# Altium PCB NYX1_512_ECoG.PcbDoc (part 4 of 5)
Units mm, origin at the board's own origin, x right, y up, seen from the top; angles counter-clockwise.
Board outline 46.64 x 13 mm, 4 copper layers (metal 2, via, metal1, electrodes), stack 0.007 mm thick; 9 components, 547 nets, 1871 pads, 0 vias.
Unrouted connection lines stored in the file: 652.
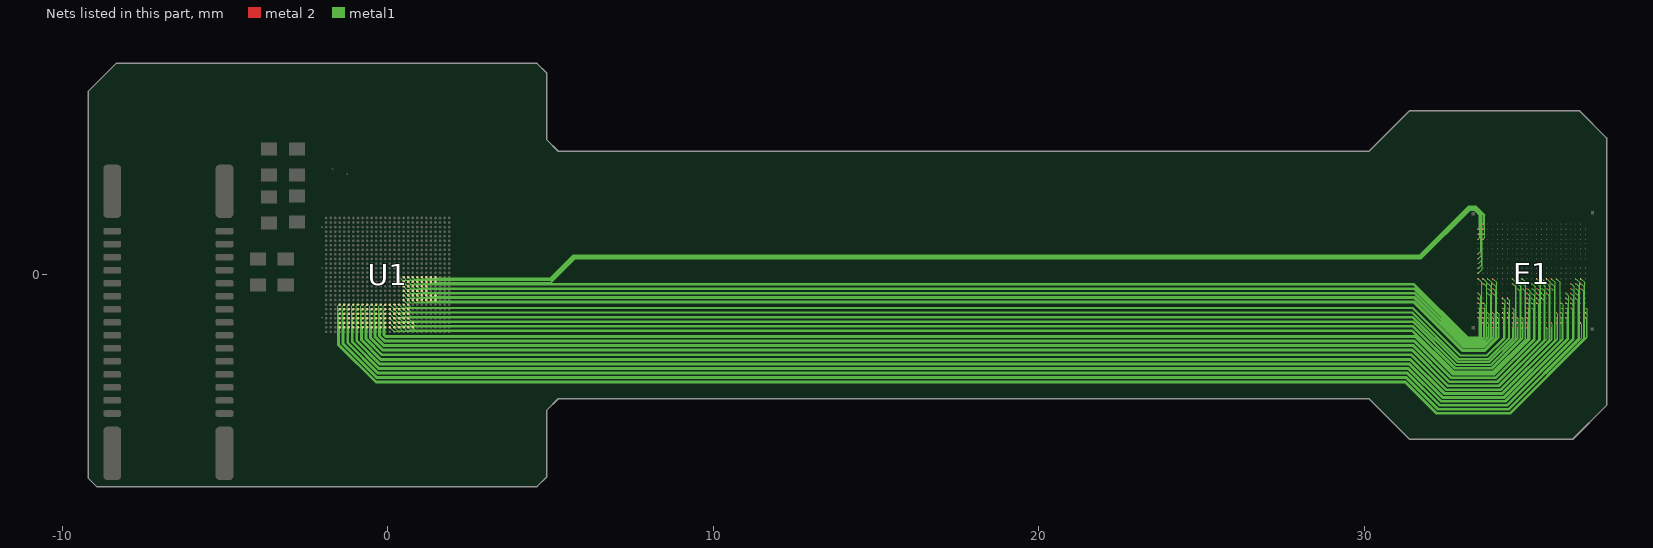
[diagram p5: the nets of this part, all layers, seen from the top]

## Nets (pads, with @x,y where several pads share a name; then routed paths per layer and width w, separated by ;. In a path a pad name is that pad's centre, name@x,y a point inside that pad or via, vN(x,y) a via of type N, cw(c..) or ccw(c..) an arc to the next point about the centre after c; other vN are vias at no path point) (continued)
el286: E1.325 pad.34@34.691,-0.425 U1.J24 | length 36.6
  metal 2 w0.012: pad.34@34.691,-0.425 E1.325@34.691,-0.406
  metal1 w0.005: U1.J24@0.77,-1.469 0.837,-1.536 3.141,-1.536 30.141,-1.536 31.486,-1.536 32.787,-2.836 33.916,-2.836 34.791,-1.962 34.791,-0.506 34.71,-0.425 pad.34@34.691,-0.425
el287: E1.326 pad.34@34.841,-0.425 U1.J25 | length 36.7
  metal 2 w0.012: pad.34@34.841,-0.425 E1.326@34.841,-0.406
  metal1 w0.005: U1.J25@0.77,-1.609 0.837,-1.676 31.468,-1.676 32.739,-2.946 33.962,-2.946 34.941,-1.967 34.941,-0.506 34.86,-0.425 pad.34@34.841,-0.425
el288: E1.460 pad.34@34.241,-1.325 U1.K20 | length 35.1
  metal 2 w0.012: pad.34@34.241,-1.325 E1.460@34.241,-1.306
  metal1 w0.005: U1.K20@0.63,-0.909 0.707,-0.986 30.141,-0.986 31.49,-0.986 32.95,-2.446 33.755,-2.446 34.281,-1.92 34.281,-1.346 34.26,-1.325 pad.34@34.241,-1.325
el289: E1.461 pad.34@34.391,-1.325 U1.K21 | length 35.3
  metal 2 w0.012: pad.34@34.391,-1.325 E1.461@34.391,-1.306
  metal1 w0.005: U1.K21@0.63,-1.049 0.707,-1.126 3.141,-1.126 ; 3.141,-1.126 31.473,-1.126 32.903,-2.556 33.8,-2.556 34.431,-1.926 34.431,-1.346 34.41,-1.325 pad.34@34.391,-1.325
el290: E1.504 pad.34@34.541,-1.625 U1.K22 | length 35.2
  metal 2 w0.012: pad.34@34.541,-1.625 E1.504@34.541,-1.606
  metal1 w0.005: U1.K22@0.63,-1.189 0.707,-1.266 31.486,-1.266 32.866,-2.646 33.838,-2.646 34.561,-1.923 34.561,-1.645 pad.34@34.541,-1.625
el291: E1.301 pad.34@34.541,-0.275 U1.K23 | length 36.7
  metal 2 w0.012: pad.34@34.541,-0.275 E1.301@34.541,-0.256
  metal1 w0.005: U1.K23@0.63,-1.329 0.707,-1.406 30.141,-1.406 31.498,-1.406 32.828,-2.736 33.875,-2.736 34.651,-1.96 34.651,-0.366 34.56,-0.275 pad.34@34.541,-0.275
el292: E1.302 pad.34@34.691,-0.275 U1.K24 | length 36.9
  metal 2 w0.012: pad.34@34.691,-0.275 E1.302@34.691,-0.256
  metal1 w0.005: U1.K24@0.63,-1.469 0.707,-1.546 3.141,-1.546 30.141,-1.546 31.482,-1.546 32.782,-2.846 33.92,-2.846 34.801,-1.966 34.801,-0.366 34.71,-0.275 pad.34@34.691,-0.275
el293: E1.303 pad.34@34.841,-0.275 U1.K25 | length 37.1
  metal 2 w0.012: pad.34@34.841,-0.275 E1.303@34.841,-0.256
  metal1 w0.005: U1.K25@0.63,-1.609 0.707,-1.686 31.464,-1.686 32.735,-2.957 33.966,-2.957 34.951,-1.971 34.951,-0.366 34.86,-0.275 pad.34@34.841,-0.275
el294: E1.437 pad.34@34.241,-1.175 U1.L20 | length 35.5
  metal 2 w0.012: pad.34@34.241,-1.175 E1.437@34.241,-1.156
  metal1 w0.005: U1.L20@0.49,-0.909 0.577,-0.996 30.141,-0.996 31.486,-0.996 32.946,-2.456 33.759,-2.456 34.291,-1.924 34.291,-1.206 34.26,-1.175 pad.34@34.241,-1.175
el295: E1.438 pad.34@34.391,-1.175 U1.L21 | length 35.6
  metal 2 w0.012: pad.34@34.391,-1.175 E1.438@34.391,-1.156
  metal1 w0.005: U1.L21@0.49,-1.049 0.577,-1.136 3.141,-1.136 30.141,-1.136 31.469,-1.136 32.899,-2.566 33.804,-2.566 34.441,-1.93 34.441,-1.206 34.41,-1.175 pad.34@34.391,-1.175
el296: E1.484 pad.34@34.541,-1.475 U1.L22 | length 35.5
  metal 2 w0.012: pad.34@34.541,-1.475 E1.484@34.541,-1.456
  metal1 w0.005: U1.L22@0.49,-1.189 0.577,-1.276 31.481,-1.276 32.862,-2.656 33.842,-2.656 34.571,-1.927 34.571,-1.505 pad.34@34.541,-1.475
el297: E1.278 pad.34@34.541,-0.125 U1.L23 | length 37
  metal 2 w0.012: pad.34@34.541,-0.125 E1.278@34.541,-0.106
  metal1 w0.005: U1.L23@0.49,-1.329 0.577,-1.416 30.141,-1.416 31.494,-1.416 32.824,-2.746 33.879,-2.746 34.661,-1.964 34.661,-0.226 34.56,-0.125 pad.34@34.541,-0.125
el298: E1.279 pad.34@34.691,-0.125 U1.L24 | length 37.2
  metal 2 w0.012: pad.34@34.691,-0.125 E1.279@34.691,-0.106
  metal1 w0.005: U1.L24@0.49,-1.469 0.577,-1.556 3.141,-1.556 30.141,-1.556 31.478,-1.556 32.778,-2.856 33.925,-2.856 34.811,-1.97 34.811,-0.226 34.71,-0.125 pad.34@34.691,-0.125
el299: E1.280 pad.34@34.841,-0.125 U1.L25 | length 37.4
  metal 2 w0.012: pad.34@34.841,-0.125 E1.280@34.841,-0.106
  metal1 w0.005: U1.L25@0.49,-1.609 0.577,-1.696 30.137,-1.696 31.46,-1.696 32.731,-2.967 33.97,-2.967 34.961,-1.976 34.961,-0.226 34.86,-0.125 pad.34@34.841,-0.125
el300: E1.414 pad.34@34.241,-1.025 U1.M20 | length 35.8
  metal 2 w0.012: pad.34@34.241,-1.025 E1.414@34.241,-1.006
  metal1 w0.005: U1.M20@0.35,-0.909 0.447,-1.006 30.141,-1.006 31.481,-1.006 32.942,-2.466 33.763,-2.466 34.301,-1.928 34.301,-1.066 34.26,-1.025 pad.34@34.241,-1.025
el301: E1.415 pad.34@34.391,-1.025 U1.M21 | length 36
  metal 2 w0.012: pad.34@34.391,-1.025 E1.415@34.391,-1.006
  metal1 w0.005: U1.M21@0.35,-1.049 0.447,-1.146 3.141,-1.146 30.141,-1.146 31.465,-1.146 32.895,-2.576 33.809,-2.576 34.451,-1.934 34.451,-1.066 34.41,-1.025 pad.34@34.391,-1.025
el302: E1.462 pad.34@34.541,-1.325 U1.M22 | length 35.8
  metal 2 w0.012: pad.34@34.541,-1.325 E1.462@34.541,-1.306
  metal1 w0.005: U1.M22@0.35,-1.189 0.447,-1.286 31.477,-1.286 32.858,-2.666 33.846,-2.666 34.581,-1.931 34.581,-1.346 34.56,-1.325 pad.34@34.541,-1.325
el303: E1.505 pad.34@34.691,-1.625 U1.M23 | length 35.6
  metal 2 w0.012: pad.34@34.691,-1.625 E1.505@34.691,-1.606
  metal1 w0.005: U1.M23@0.35,-1.329 0.447,-1.426 3.141,-1.426 30.141,-1.426 31.49,-1.426 32.82,-2.756 33.883,-2.756 34.711,-1.929 34.711,-1.645 pad.34@34.691,-1.625
el304: E1.506 pad.34@34.841,-1.625 U1.M24 | length 35.8
  metal 2 w0.012: pad.34@34.841,-1.625 E1.506@34.841,-1.606
  metal1 w0.005: U1.M24@0.35,-1.469 0.447,-1.566 3.141,-1.566 30.141,-1.566 31.473,-1.566 32.774,-2.866 33.929,-2.866 34.861,-1.934 34.861,-1.645 pad.34@34.841,-1.625
el305: E1.507 pad.34@34.991,-1.625 U1.M25 | length 36
  metal 2 w0.012: pad.34@34.991,-1.625 E1.507@34.991,-1.606
  metal1 w0.005: U1.M25@0.35,-1.609 0.447,-1.706 3.141,-1.706 31.456,-1.706 32.726,-2.977 33.974,-2.977 35.011,-1.94 35.011,-1.645 pad.34@34.991,-1.625
el306: E1.391 pad.34@34.241,-0.875 U1.N20 | length 36.1
  metal 2 w0.012: pad.34@34.241,-0.875 E1.391@34.241,-0.856
  metal1 w0.005: U1.N20@0.21,-0.909 0.317,-1.016 30.141,-1.016 31.477,-1.016 32.937,-2.476 33.767,-2.476 34.311,-1.933 34.311,-0.926 34.26,-0.875 pad.34@34.241,-0.875
el307: E1.392 pad.34@34.391,-0.875 U1.N21 | length 36.3
  metal 2 w0.012: pad.34@34.391,-0.875 E1.392@34.391,-0.856
  metal1 w0.005: U1.N21@0.21,-1.049 0.317,-1.156 3.141,-1.156 30.141,-1.156 31.46,-1.156 32.891,-2.586 33.813,-2.586 34.461,-1.938 34.461,-0.926 34.41,-0.875 pad.34@34.391,-0.875
el308: E1.439 pad.34@34.541,-1.175 U1.N22 | length 36.1
  metal 2 w0.012: pad.34@34.541,-1.175 E1.439@34.541,-1.156
  metal1 w0.005: U1.N22@0.21,-1.189 0.317,-1.296 31.473,-1.296 32.853,-2.676 33.85,-2.676 34.591,-1.935 34.591,-1.206 34.56,-1.175 pad.34@34.541,-1.175
el309: E1.485 pad.34@34.691,-1.475 U1.N23 | length 35.9
  metal 2 w0.012: pad.34@34.691,-1.475 E1.485@34.691,-1.456
  metal1 w0.005: U1.N23@0.21,-1.329 0.317,-1.436 3.141,-1.436 30.141,-1.436 31.486,-1.436 32.816,-2.766 33.887,-2.766 34.721,-1.933 34.721,-1.505 pad.34@34.691,-1.475
el310: E1.486 pad.34@34.841,-1.475 U1.N24 | length 36.1
  metal 2 w0.012: pad.34@34.841,-1.475 E1.486@34.841,-1.456
  metal1 w0.005: U1.N24@0.21,-1.469 0.317,-1.576 3.141,-1.576 30.141,-1.576 31.469,-1.576 32.77,-2.876 33.933,-2.876 34.871,-1.938 34.871,-1.505 pad.34@34.841,-1.475
el311: E1.487 pad.34@34.991,-1.475 U1.N25 | length 36.3
  metal 2 w0.012: pad.34@34.991,-1.475 E1.487@34.991,-1.456
  metal1 w0.005: U1.N25@0.21,-1.609 0.317,-1.716 3.141,-1.716 31.452,-1.716 32.722,-2.987 33.978,-2.987 35.021,-1.944 35.021,-1.505 pad.34@34.991,-1.475
el312: E1.368 pad.34@34.241,-0.725 U1.P20 | length 36.4
  metal 2 w0.012: pad.34@34.241,-0.725 E1.368@34.241,-0.706
  metal1 w0.005: U1.P20@0.07,-0.909 0.188,-1.026 30.141,-1.026 31.473,-1.026 32.933,-2.486 33.771,-2.486 34.321,-1.937 34.321,-0.786 34.26,-0.725 pad.34@34.241,-0.725
el313: E1.369 pad.34@34.391,-0.725 U1.P21 | length 36.6
  metal 2 w0.012: pad.34@34.391,-0.725 E1.369@34.391,-0.706
  metal1 w0.005: U1.P21@0.07,-1.049 0.188,-1.166 3.141,-1.166 30.141,-1.166 31.456,-1.166 32.887,-2.596 33.817,-2.596 34.471,-1.942 34.471,-0.786 34.41,-0.725 pad.34@34.391,-0.725
el314: E1.416 pad.34@34.541,-1.025 U1.P22 | length 36.4
  metal 2 w0.012: pad.34@34.541,-1.025 E1.416@34.541,-1.006
  metal1 w0.005: U1.P22@0.07,-1.189 0.188,-1.306 31.469,-1.306 32.849,-2.686 33.854,-2.686 34.601,-1.94 34.601,-1.066 34.56,-1.025 pad.34@34.541,-1.025
el315: E1.463 pad.34@34.691,-1.325 U1.P23 | length 36.3
  metal 2 w0.012: pad.34@34.691,-1.325 E1.463@34.691,-1.306
  metal1 w0.005: U1.P23@0.07,-1.329 0.188,-1.446 3.141,-1.446 30.141,-1.446 31.481,-1.446 32.812,-2.776 33.891,-2.776 34.731,-1.937 34.731,-1.346 34.71,-1.325 pad.34@34.691,-1.325
el316: E1.464 pad.34@34.841,-1.325 U1.P24 | length 36.5
  metal 2 w0.012: pad.34@34.841,-1.325 E1.464@34.841,-1.306
  metal1 w0.005: U1.P24@0.07,-1.469 0.188,-1.586 3.141,-1.586 31.465,-1.586 32.765,-2.886 33.937,-2.886 34.881,-1.942 34.881,-1.346 34.86,-1.325 pad.34@34.841,-1.325
el317: E1.465 pad.34@34.991,-1.325 U1.P25 | length 36.6
  metal 2 w0.012: pad.34@34.991,-1.325 E1.465@34.991,-1.306
  metal1 w0.005: U1.P25@0.07,-1.609 0.188,-1.726 3.141,-1.726 31.448,-1.726 32.718,-2.997 33.983,-2.997 35.031,-1.948 35.031,-1.346 ; pad.34@34.991,-1.325 35.01,-1.325 35.031,-1.345
el318: E1.327 pad.34@34.991,-0.425 U1.R20 | length 38.8
  metal 2 w0.012: pad.34@34.991,-0.425 E1.327@34.991,-0.406
  metal1 w0.005: U1.R20@-0.07,-0.909 -0.128,-0.966 -0.128,-1.858 -0.075,-1.911 31.547,-1.911 32.693,-3.057 34.007,-3.057 35.091,-1.973 35.091,-0.506 35.01,-0.425 pad.34@34.991,-0.425
el319: E1.350 pad.34@34.991,-0.575 U1.R21 | length 38.4
  metal 2 w0.012: pad.34@34.991,-0.575 E1.350@34.991,-0.556
  metal1 w0.005: U1.R21@-0.07,-1.049 -0.118,-1.096 -0.118,-1.854 -0.07,-1.901 31.551,-1.901 32.697,-3.047 34.003,-3.047 35.081,-1.969 35.081,-0.646 35.01,-0.575 pad.34@34.991,-0.575
el320: E1.373 pad.34@34.991,-0.725 U1.R22 | length 38.1
  metal 2 w0.012: pad.34@34.991,-0.725 E1.373@34.991,-0.706
  metal1 w0.005: U1.R22@-0.07,-1.189 -0.108,-1.226 -0.108,-1.85 -0.066,-1.891 31.556,-1.891 32.701,-3.037 33.999,-3.037 35.071,-1.965 35.071,-0.786 35.01,-0.725 pad.34@34.991,-0.725
el321: E1.396 pad.34@34.991,-0.875 U1.R23 | length 37.8
  metal 2 w0.012: pad.34@34.991,-0.875 E1.396@34.991,-0.856
  metal1 w0.005: U1.R23@-0.07,-1.329 -0.098,-1.356 -0.098,-1.846 -0.062,-1.881 31.56,-1.881 32.705,-3.027 33.995,-3.027 35.061,-1.961 35.061,-0.926 35.01,-0.875 pad.34@34.991,-0.875
el322: E1.419 pad.34@34.991,-1.025 U1.R24 | length 37.4
  metal 2 w0.012: pad.34@34.991,-1.025 E1.419@34.991,-1.006
  metal1 w0.005: U1.R24@-0.07,-1.469 -0.088,-1.486 -0.088,-1.842 -0.058,-1.871 31.564,-1.871 32.709,-3.017 33.991,-3.017 35.051,-1.956 35.051,-1.066 35.01,-1.025 pad.34@34.991,-1.025
el323: E1.442 pad.34@34.991,-1.175 U1.R25 | length 37.1
  metal 2 w0.012: pad.34@34.991,-1.175 E1.442@34.991,-1.156
  metal1 w0.005: U1.R25@-0.07,-1.609 -0.07,-1.842 -0.058,-1.854 31.561,-1.854 32.714,-3.007 33.987,-3.007 35.041,-1.952 35.041,-1.206 35.01,-1.175 pad.34@34.991,-1.175
el324: E1.305 pad.34@35.141,-0.275 U1.T20 | length 39.3
  metal 2 w0.012: pad.34@35.141,-0.275 E1.305@35.141,-0.256
  metal1 w0.005: U1.T20@-0.21,-0.909 -0.268,-0.966 -0.268,-1.888 -0.104,-2.051 31.516,-2.051 32.641,-3.177 34.057,-3.177 35.251,-1.983 35.251,-0.366 35.16,-0.275 pad.34@35.141,-0.275
el325: E1.328 pad.34@35.141,-0.425 U1.T21 | length 39
  metal 2 w0.012: pad.34@35.141,-0.425 E1.328@35.141,-0.406
  metal1 w0.005: U1.T21@-0.21,-1.049 -0.258,-1.096 -0.258,-1.884 -0.1,-2.041 31.521,-2.041 32.646,-3.167 34.053,-3.167 35.241,-1.979 35.241,-0.506 35.16,-0.425 pad.34@35.141,-0.425
el326: E1.351 pad.34@35.141,-0.575 U1.T22 | length 38.7
  metal 2 w0.012: pad.34@35.141,-0.575 E1.351@35.141,-0.556
  metal1 w0.005: U1.T22@-0.21,-1.189 -0.248,-1.226 -0.248,-1.88 -0.096,-2.031 31.525,-2.031 32.65,-3.157 34.049,-3.157 35.231,-1.974 35.231,-0.646 35.16,-0.575 pad.34@35.141,-0.575
el327: E1.374 pad.34@35.141,-0.725 U1.T23 | length 38.3
  metal 2 w0.012: pad.34@35.141,-0.725 E1.374@35.141,-0.706
  metal1 w0.005: U1.T23@-0.21,-1.329 -0.238,-1.356 -0.238,-1.875 -0.092,-2.021 31.529,-2.021 32.655,-3.147 34.045,-3.147 35.221,-1.97 35.221,-0.786 35.16,-0.725 pad.34@35.141,-0.725
el328: E1.397 pad.34@35.141,-0.875 U1.T24 | length 38
  metal 2 w0.012: pad.34@35.141,-0.875 E1.397@35.141,-0.856
  metal1 w0.005: U1.T24@-0.21,-1.469 -0.228,-1.486 -0.228,-1.871 -0.088,-2.011 31.534,-2.011 32.659,-3.137 34.041,-3.137 35.211,-1.966 35.211,-0.926 35.16,-0.875 pad.34@35.141,-0.875
el329: E1.420 pad.34@35.141,-1.025 U1.T25 | length 37.7
  metal 2 w0.012: pad.34@35.141,-1.025 E1.420@35.141,-1.006
  metal1 w0.005: U1.T25@-0.21,-1.609 -0.21,-1.875 -0.091,-1.994 31.53,-1.994 32.663,-3.127 34.036,-3.127 35.201,-1.962 35.201,-1.066 35.16,-1.025 pad.34@35.141,-1.025
el330: E1.283 pad.34@35.291,-0.125 U1.U20 | length 39.9
  metal 2 w0.012: pad.34@35.291,-0.125 E1.283@35.291,-0.106
  metal1 w0.005: U1.U20@-0.35,-0.909 -0.408,-0.966 -0.408,-1.918 -0.134,-2.192 31.486,-2.192 32.592,-3.298 34.106,-3.298 35.411,-1.992 35.411,-0.226 35.31,-0.125 pad.34@35.291,-0.125
el331: E1.306 pad.34@35.291,-0.275 U1.U21 | length 39.6
  metal 2 w0.012: pad.34@35.291,-0.275 E1.306@35.291,-0.256
  metal1 w0.005: U1.U21@-0.35,-1.049 -0.398,-1.096 -0.398,-1.913 -0.129,-2.182 31.49,-2.182 32.596,-3.288 34.102,-3.288 35.401,-1.988 35.401,-0.366 35.31,-0.275 pad.34@35.291,-0.275
el332: E1.329 pad.34@35.291,-0.425 U1.U22 | length 39.2
  metal 2 w0.012: pad.34@35.291,-0.425 E1.329@35.291,-0.406
  metal1 w0.005: U1.U22@-0.35,-1.189 -0.388,-1.226 -0.388,-1.909 -0.125,-2.172 30.696,-2.172 31.495,-2.172 32.601,-3.278 34.098,-3.278 35.391,-1.984 35.391,-0.506 35.31,-0.425 pad.34@35.291,-0.425
el333: E1.352 pad.34@35.291,-0.575 U1.U23 | length 38.9
  metal 2 w0.012: pad.34@35.291,-0.575 E1.352@35.291,-0.556
  metal1 w0.005: U1.U23@-0.35,-1.329 -0.378,-1.356 -0.378,-1.905 -0.121,-2.162 31.499,-2.162 32.605,-3.268 34.093,-3.268 35.381,-1.98 35.381,-0.646 35.31,-0.575 pad.34@35.291,-0.575
el334: E1.375 pad.34@35.291,-0.725 U1.U24 | length 38.6
  metal 2 w0.012: pad.34@35.291,-0.725 E1.375@35.291,-0.706
  metal1 w0.005: U1.U24@-0.35,-1.469 -0.368,-1.486 -0.368,-1.901 -0.117,-2.152 30.705,-2.152 31.503,-2.152 32.609,-3.258 34.089,-3.258 35.371,-1.976 35.371,-0.786 35.31,-0.725 pad.34@35.291,-0.725
el335: E1.398 pad.34@35.291,-0.875 U1.U25 | length 38.2
  metal 2 w0.012: pad.34@35.291,-0.875 E1.398@35.291,-0.856
  metal1 w0.005: U1.U25@-0.35,-1.609 -0.35,-1.904 -0.121,-2.134 29.636,-2.134 30.701,-2.134 31.499,-2.134 32.613,-3.248 34.085,-3.248 35.361,-1.972 35.361,-0.926 35.31,-0.875 pad.34@35.291,-0.875
el336: E1.511 pad.34@35.591,-1.625 U1.V20 | length 38.8
  metal 2 w0.012: pad.34@35.591,-1.625 E1.511@35.591,-1.606
  metal1 w0.005: U1.V20@-0.49,-0.909 -0.548,-0.966 -0.548,-1.947 -0.164,-2.331 31.454,-2.331 32.542,-3.418 34.155,-3.418 35.611,-1.962 35.611,-1.645 pad.34@35.591,-1.625
el337: E1.284 pad.34@35.441,-0.125 U1.V21 | length 40.2
  metal 2 w0.012: pad.34@35.441,-0.125 E1.284@35.441,-0.106
  metal1 w0.005: U1.V21@-0.49,-1.049 -0.538,-1.096 -0.538,-1.943 -0.16,-2.321 31.458,-2.321 32.546,-3.408 34.151,-3.408 35.561,-1.998 35.561,-0.226 35.46,-0.125 pad.34@35.441,-0.125
el338: E1.307 pad.34@35.441,-0.275 U1.V22 | length 39.8
  metal 2 w0.012: pad.34@35.441,-0.275 E1.307@35.441,-0.256
  metal1 w0.005: U1.V22@-0.49,-1.189 -0.528,-1.226 -0.528,-1.939 -0.166,-2.301 31.453,-2.301 32.55,-3.398 34.146,-3.398 35.551,-1.994 35.551,-0.366 35.46,-0.275 pad.34@35.441,-0.275
el339: E1.330 pad.34@35.441,-0.425 U1.V23 | length 39.5
  metal 2 w0.012: pad.34@35.441,-0.425 E1.330@35.441,-0.406
  metal1 w0.005: U1.V23@-0.49,-1.329 -0.518,-1.356 -0.518,-1.935 -0.161,-2.291 31.457,-2.291 32.554,-3.388 34.142,-3.388 35.541,-1.99 35.541,-0.506 35.46,-0.425 pad.34@35.441,-0.425
el340: E1.353 pad.34@35.441,-0.575 U1.V24 | length 39.2
  metal 2 w0.012: pad.34@35.441,-0.575 E1.353@35.441,-0.556
  metal1 w0.005: U1.V24@-0.49,-1.469 -0.508,-1.486 -0.508,-1.931 -0.157,-2.281 31.461,-2.281 32.558,-3.378 34.138,-3.378 35.531,-1.986 35.531,-0.646 35.46,-0.575 pad.34@35.441,-0.575
el341: E1.376 pad.34@35.441,-0.725 U1.V25 | length 38.8
  metal 2 w0.012: pad.34@35.441,-0.725 E1.376@35.441,-0.706
  metal1 w0.005: U1.V25@-0.49,-1.609 -0.49,-1.934 -0.153,-2.271 3.141,-2.271 29.641,-2.271 31.465,-2.271 32.562,-3.368 34.134,-3.368 35.521,-1.981 35.521,-0.786 35.46,-0.725 pad.34@35.441,-0.725
el342: E1.492 pad.34@35.741,-1.475 U1.W20 | length 39.4
  metal 2 w0.012: pad.34@35.741,-1.475 E1.492@35.741,-1.456
  metal1 w0.005: U1.W20@-0.63,-0.909 -0.688,-0.966 -0.688,-1.977 -0.194,-2.471 31.425,-2.471 32.492,-3.538 34.204,-3.538 35.771,-1.972 35.771,-1.505 pad.34@35.741,-1.475
el343: E1.512 pad.34@35.741,-1.625 U1.W21 | length 39
  metal 2 w0.012: pad.34@35.741,-1.625 E1.512@35.741,-1.606
  metal1 w0.005: U1.W21@-0.63,-1.049 -0.678,-1.096 -0.678,-1.973 -0.189,-2.461 31.429,-2.461 32.496,-3.528 34.2,-3.528 35.761,-1.968 35.761,-1.645 pad.34@35.741,-1.625
el344: E1.285 pad.34@35.591,-0.125 U1.W22 | length 40.4
  metal 2 w0.012: pad.34@35.591,-0.125 E1.285@35.591,-0.106
  metal1 w0.005: U1.W22@-0.63,-1.189 -0.668,-1.226 -0.668,-1.969 -0.185,-2.451 31.433,-2.451 32.5,-3.518 34.196,-3.518 35.711,-2.004 35.711,-0.226 35.61,-0.125 pad.34@35.591,-0.125
el345: E1.308 pad.34@35.591,-0.275 U1.W23 | length 40.1
  metal 2 w0.012: pad.34@35.591,-0.275 E1.308@35.591,-0.256
  metal1 w0.005: U1.W23@-0.63,-1.329 -0.658,-1.356 -0.658,-1.965 -0.181,-2.441 30.641,-2.441 31.437,-2.441 32.504,-3.508 34.192,-3.508 35.701,-1.999 35.701,-0.366 35.61,-0.275 pad.34@35.591,-0.275
el346: E1.331 pad.34@35.591,-0.425 U1.W24 | length 39.7
  metal 2 w0.012: pad.34@35.591,-0.425 E1.331@35.591,-0.406
  metal1 w0.005: U1.W24@-0.63,-1.469 -0.648,-1.486 -0.648,-1.961 -0.177,-2.431 30.645,-2.431 31.441,-2.431 32.509,-3.498 34.188,-3.498 35.691,-1.995 35.691,-0.506 35.61,-0.425 pad.34@35.591,-0.425
el347: E1.354 pad.34@35.591,-0.575 U1.W25 | length 39.4
  metal 2 w0.012: pad.34@35.591,-0.575 E1.354@35.591,-0.556
  metal1 w0.005: U1.W25@-0.63,-1.609 -0.63,-1.964 -0.18,-2.414 30.641,-2.414 ; 30.646,-2.414 31.438,-2.414 32.513,-3.488 34.184,-3.488 35.681,-1.991 35.681,-0.646 35.61,-0.575 pad.34@35.591,-0.575
el348: E1.448 pad.34@35.891,-1.175 U1.Y20 | length 40.1
  metal 2 w0.012: pad.34@35.891,-1.175 E1.448@35.891,-1.156
  metal1 w0.005: U1.Y20@-0.77,-0.909 -0.828,-0.966 -0.828,-2.007 -0.223,-2.611 31.395,-2.611 32.442,-3.659 34.254,-3.659 35.941,-1.972 35.941,-1.206 35.91,-1.175 pad.34@35.891,-1.175
el349: E1.471 pad.34@35.891,-1.325 U1.Y21 | length 39.8
  metal 2 w0.012: pad.34@35.891,-1.325 E1.471@35.891,-1.306
  metal1 w0.005: U1.Y21@-0.77,-1.049 -0.818,-1.096 -0.818,-2.003 -0.219,-2.601 31.399,-2.601 32.446,-3.649 34.25,-3.649 35.931,-1.968 35.931,-1.346 35.91,-1.325 pad.34@35.891,-1.325
el350: E1.493 pad.34@35.891,-1.475 U1.Y22 | length 39.4
  metal 2 w0.012: pad.34@35.891,-1.475 E1.493@35.891,-1.456
  metal1 w0.005: U1.Y22@-0.77,-1.189 -0.808,-1.226 -0.808,-1.999 -0.215,-2.591 31.403,-2.591 32.451,-3.639 34.246,-3.639 35.921,-1.963 35.921,-1.505 pad.34@35.891,-1.475
el351: E1.286 pad.34@35.741,-0.125 U1.Y23 | length 40.6
  metal 2 w0.012: pad.34@35.741,-0.125 E1.286@35.741,-0.106
  metal1 w0.005: U1.Y23@-0.77,-1.329 -0.798,-1.356 -0.798,-1.994 -0.211,-2.581 31.407,-2.581 32.455,-3.629 34.242,-3.629 35.861,-2.009 35.861,-0.226 35.76,-0.125 pad.34@35.741,-0.125
el352: E1.309 pad.34@35.741,-0.275 U1.Y24 | length 40.3
  metal 2 w0.012: pad.34@35.741,-0.275 E1.309@35.741,-0.256
  metal1 w0.005: U1.Y24@-0.77,-1.469 -0.788,-1.486 -0.788,-1.99 -0.207,-2.571 31.411,-2.571 32.459,-3.619 34.238,-3.619 35.851,-2.005 35.851,-0.366 35.76,-0.275 pad.34@35.741,-0.275
el353: E1.332 pad.34@35.741,-0.425 U1.Y25 | length 40
  metal 2 w0.012: pad.34@35.741,-0.425 E1.332@35.741,-0.406
  metal1 w0.005: U1.Y25@-0.77,-1.609 -0.77,-1.994 -0.21,-2.554 30.61,-2.554 ; 30.614,-2.554 31.408,-2.554 32.463,-3.609 34.233,-3.609 35.841,-2.001 35.841,-0.506 35.76,-0.425 pad.34@35.741,-0.425
el354: E1.403 pad.34@36.041,-0.875 U1.AA20 | length 40.9
  metal 2 w0.012: pad.34@36.041,-0.875 E1.403@36.041,-0.856
  metal1 w0.005: U1.AA20@-0.91,-0.909 -0.968,-0.966 -0.968,-2.037 -0.253,-2.751 30.567,-2.751 31.365,-2.751 32.393,-3.779 34.304,-3.779 36.111,-1.971 36.111,-0.926 36.06,-0.875 pad.34@36.041,-0.875
el355: E1.426 pad.34@36.041,-1.025 U1.AA21 | length 40.5
  metal 2 w0.012: pad.34@36.041,-1.025 E1.426@36.041,-1.006
  metal1 w0.005: U1.AA21@-0.91,-1.049 -0.958,-1.096 -0.958,-2.032 -0.249,-2.741 30.571,-2.741 ; 30.567,-2.741 31.369,-2.741 32.397,-3.769 34.3,-3.769 36.101,-1.967 36.101,-1.066 36.06,-1.025 pad.34@36.041,-1.025
el356: E1.449 pad.34@36.041,-1.175 U1.AA22 | length 40.2
  metal 2 w0.012: pad.34@36.041,-1.175 E1.449@36.041,-1.156
  metal1 w0.005: U1.AA22@-0.91,-1.189 -0.948,-1.226 -0.948,-2.028 -0.245,-2.731 30.575,-2.731 31.373,-2.731 32.401,-3.759 34.296,-3.759 36.091,-1.963 36.091,-1.206 36.06,-1.175 pad.34@36.041,-1.175
el357: E1.472 pad.34@36.041,-1.325 U1.AA23 | length 39.9
  metal 2 w0.012: pad.34@36.041,-1.325 E1.472@36.041,-1.306
  metal1 w0.005: U1.AA23@-0.91,-1.329 -0.938,-1.356 -0.938,-2.024 -0.241,-2.721 30.58,-2.721 ; 30.575,-2.721 31.378,-2.721 32.405,-3.749 34.291,-3.749 36.081,-1.959 36.081,-1.346 36.06,-1.325 pad.34@36.041,-1.325
el358: E1.494 pad.34@36.041,-1.475 U1.AA24 | length 39.5
  metal 2 w0.012: pad.34@36.041,-1.475 E1.494@36.041,-1.456
  metal1 w0.005: U1.AA24@-0.91,-1.469 -0.928,-1.486 -0.928,-2.02 -0.236,-2.711 31.382,-2.711 32.409,-3.739 34.287,-3.739 36.071,-1.955 36.071,-1.505 pad.34@36.041,-1.475
el359: E1.287 pad.34@35.891,-0.125 U1.AA25 | length 40.7
  metal 2 w0.012: pad.34@35.891,-0.125 E1.287@35.891,-0.106
  metal1 w0.005: U1.AA25@-0.91,-1.609 -0.91,-2.023 -0.24,-2.694 4.853,-2.694 29.641,-2.694 31.378,-2.694 32.413,-3.729 34.283,-3.729 36.011,-2.001 36.011,-0.226 35.91,-0.125 pad.34@35.891,-0.125
el360: E1.358 pad.34@36.191,-0.575 U1.AB20 | length 41.6
  metal 2 w0.012: pad.34@36.191,-0.575 E1.358@36.191,-0.556
  metal1 w0.005: U1.AB20@-1.05,-0.909 -1.108,-0.966 -1.108,-2.066 -0.283,-2.891 3.141,-2.891 29.641,-2.891 31.335,-2.891 32.344,-3.9 34.353,-3.9 36.281,-1.971 36.281,-0.646 36.21,-0.575 pad.34@36.191,-0.575
el361: E1.381 pad.34@36.191,-0.725 U1.AB21 | length 41.3
  metal 2 w0.012: pad.34@36.191,-0.725 E1.381@36.191,-0.706
  metal1 w0.005: U1.AB21@-1.05,-1.049 -1.098,-1.096 -1.098,-2.062 -0.279,-2.881 3.141,-2.881 29.641,-2.881 31.34,-2.881 32.348,-3.89 34.348,-3.89 36.271,-1.967 36.271,-0.786 36.21,-0.725 pad.34@36.191,-0.725
el362: E1.404 pad.34@36.191,-0.875 U1.AB22 | length 40.9
  metal 2 w0.012: pad.34@36.191,-0.875 E1.404@36.191,-0.856
  metal1 w0.005: U1.AB22@-1.05,-1.189 -1.088,-1.226 -1.088,-2.058 -0.275,-2.871 3.141,-2.871 29.641,-2.871 31.344,-2.871 32.352,-3.88 34.344,-3.88 36.261,-1.963 36.261,-0.926 36.21,-0.875 pad.34@36.191,-0.875
el363: E1.427 pad.34@36.191,-1.025 U1.AB23 | length 40.6
  metal 2 w0.012: pad.34@36.191,-1.025 E1.427@36.191,-1.006
  metal1 w0.005: U1.AB23@-1.05,-1.329 -1.078,-1.356 -1.078,-2.054 -0.27,-2.861 31.348,-2.861 32.356,-3.87 34.34,-3.87 36.251,-1.959 36.251,-1.066 36.21,-1.025 pad.34@36.191,-1.025
el364: E1.450 pad.34@36.191,-1.175 U1.AB24 | length 40.3
  metal 2 w0.012: pad.34@36.191,-1.175 E1.450@36.191,-1.156
  metal1 w0.005: U1.AB24@-1.05,-1.469 -1.068,-1.486 -1.068,-2.05 -0.266,-2.851 4.854,-2.851 ; 4.858,-2.851 31.352,-2.851 32.36,-3.86 34.336,-3.86 36.241,-1.955 36.241,-1.206 36.21,-1.175 pad.34@36.191,-1.175
el365: E1.473 pad.34@36.191,-1.325 U1.AB25 | length 39.9
  metal 2 w0.012: pad.34@36.191,-1.325 E1.473@36.191,-1.306
  metal1 w0.005: U1.AB25@-1.05,-1.609 -1.05,-2.053 -0.27,-2.834 31.349,-2.834 32.365,-3.85 34.332,-3.85 36.231,-1.95 36.231,-1.346 36.21,-1.325 pad.34@36.191,-1.325
el366: E1.313 pad.34@36.341,-0.275 U1.AC20 | length 42.3
  metal 2 w0.012: pad.34@36.341,-0.275 E1.313@36.341,-0.256
  metal1 w0.005: U1.AC20@-1.19,-0.909 -1.248,-0.966 -1.248,-2.096 -0.313,-3.031 31.306,-3.031 32.294,-4.02 34.402,-4.02 36.451,-1.971 36.451,-0.366 36.36,-0.275 pad.34@36.341,-0.275
el367: E1.336 pad.34@36.341,-0.425 U1.AC21 | length 42
  metal 2 w0.012: pad.34@36.341,-0.425 E1.336@36.341,-0.406
  metal1 w0.005: U1.AC21@-1.19,-1.049 -1.238,-1.096 -1.238,-2.092 -0.308,-3.021 31.31,-3.021 32.298,-4.01 34.398,-4.01 36.441,-1.967 36.441,-0.506 36.36,-0.425 pad.34@36.341,-0.425
el368: E1.359 pad.34@36.341,-0.575 U1.AC22 | length 41.7
  metal 2 w0.012: pad.34@36.341,-0.575 E1.359@36.341,-0.556
  metal1 w0.005: U1.AC22@-1.19,-1.189 -1.228,-1.226 -1.228,-2.088 -0.304,-3.011 31.314,-3.011 32.302,-4 34.394,-4 36.431,-1.963 36.431,-0.646 36.36,-0.575 pad.34@36.341,-0.575
el369: E1.382 pad.34@36.341,-0.725 U1.AC23 | length 41.3
  metal 2 w0.012: pad.34@36.341,-0.725 E1.382@36.341,-0.706
  metal1 w0.005: U1.AC23@-1.19,-1.329 -1.218,-1.356 -1.218,-2.084 -0.3,-3.001 31.318,-3.001 32.307,-3.99 34.39,-3.99 36.421,-1.958 36.421,-0.786 36.36,-0.725 pad.34@36.341,-0.725
el370: E1.405 pad.34@36.341,-0.875 U1.AC24 | length 41
  metal 2 w0.012: pad.34@36.341,-0.875 E1.405@36.341,-0.856
  metal1 w0.005: U1.AC24@-1.19,-1.469 -1.208,-1.486 -1.208,-2.08 -0.296,-2.991 31.322,-2.991 32.311,-3.98 34.386,-3.98 36.411,-1.954 36.411,-0.926 36.36,-0.875 pad.34@36.341,-0.875
el371: E1.428 pad.34@36.341,-1.025 U1.AC25 | length 40.7
  metal 2 w0.012: pad.34@36.341,-1.025 E1.428@36.341,-1.006
  metal1 w0.005: U1.AC25@-1.19,-1.609 -1.19,-2.083 -0.299,-2.974 3.141,-2.974 29.641,-2.974 30.489,-2.974 31.319,-2.974 32.315,-3.97 34.382,-3.97 36.401,-1.95 36.401,-1.066 36.36,-1.025 pad.34@36.341,-1.025
el372: E1.498 pad.34@36.641,-1.475 U1.AD20 | length 41.5
  metal 2 w0.012: pad.34@36.641,-1.475 E1.498@36.641,-1.456
  metal1 w0.005: U1.AD20@-1.33,-0.909 -1.388,-0.966 -1.388,-2.126 -0.342,-3.171 31.276,-3.171 32.245,-4.141 34.451,-4.141 36.671,-1.921 36.671,-1.505 pad.34@36.641,-1.475
el373: E1.291 pad.34@36.491,-0.125 U1.AD21 | length 42.7
  metal 2 w0.012: pad.34@36.491,-0.125 E1.291@36.491,-0.106
  metal1 w0.005: U1.AD21@-1.33,-1.049 -1.378,-1.096 -1.378,-2.122 -0.338,-3.161 31.28,-3.161 32.249,-4.131 34.447,-4.131 36.611,-1.966 36.611,-0.226 36.51,-0.125 pad.34@36.491,-0.125
el374: E1.314 pad.34@36.491,-0.275 U1.AD22 | length 42.4
  metal 2 w0.012: pad.34@36.491,-0.275 E1.314@36.491,-0.256
  metal1 w0.005: U1.AD22@-1.33,-1.189 -1.368,-1.226 -1.368,-2.118 -0.334,-3.151 31.284,-3.151 32.254,-4.121 34.443,-4.121 36.601,-1.962 36.601,-0.366 36.51,-0.275 pad.34@36.491,-0.275
el375: E1.337 pad.34@36.491,-0.425 U1.AD23 | length 42.1
  metal 2 w0.012: pad.34@36.491,-0.425 E1.337@36.491,-0.406
  metal1 w0.005: U1.AD23@-1.33,-1.329 -1.358,-1.356 -1.358,-2.113 -0.33,-3.141 31.288,-3.141 32.258,-4.111 34.439,-4.111 36.591,-1.958 36.591,-0.506 36.51,-0.425 pad.34@36.491,-0.425
el376: E1.360 pad.34@36.491,-0.575 U1.AD24 | length 41.7
  metal 2 w0.012: pad.34@36.491,-0.575 E1.360@36.491,-0.556
  metal1 w0.005: U1.AD24@-1.33,-1.469 -1.348,-1.486 -1.348,-2.109 -0.326,-3.131 3.141,-3.131 29.641,-3.131 31.292,-3.131 32.262,-4.101 34.435,-4.101 36.581,-1.954 36.581,-0.646 36.51,-0.575 pad.34@36.491,-0.575
el377: E1.383 pad.34@36.491,-0.725 U1.AD25 | length 41.4
  metal 2 w0.012: pad.34@36.491,-0.725 E1.383@36.491,-0.706
  metal1 w0.005: U1.AD25@-1.33,-1.609 -1.33,-2.113 -0.329,-3.114 3.141,-3.114 29.641,-3.114 31.289,-3.114 32.266,-4.091 34.43,-4.091 36.571,-1.95 36.571,-0.786 36.51,-0.725 pad.34@36.491,-0.725
el378: E1.431 pad.34@36.791,-1.025 U1.AE20 | length 42.4
  metal 2 w0.012: pad.34@36.791,-1.025 E1.431@36.791,-1.006
  metal1 w0.005: U1.AE20@-1.47,-0.909 -1.528,-0.966 -1.528,-2.156 -0.372,-3.311 3.141,-3.311 29.575,-3.311 31.246,-3.311 32.196,-4.261 34.501,-4.261 36.851,-1.91 36.851,-1.066 36.81,-1.025 pad.34@36.791,-1.025
el379: E1.454 pad.34@36.791,-1.175 U1.AE21 | length 42.1
  metal 2 w0.012: pad.34@36.791,-1.175 E1.454@36.791,-1.156
  metal1 w0.005: U1.AE21@-1.47,-1.049 -1.518,-1.096 -1.518,-2.151 -0.368,-3.301 3.141,-3.301 29.579,-3.301 31.25,-3.301 32.2,-4.251 34.497,-4.251 36.841,-1.906 36.841,-1.206 36.81,-1.175 pad.34@36.791,-1.175
el380: E1.477 pad.34@36.791,-1.325 U1.AE22 | length 41.8
  metal 2 w0.012: pad.34@36.791,-1.325 E1.477@36.791,-1.306
  metal1 w0.005: U1.AE22@-1.47,-1.189 -1.508,-1.226 -1.508,-2.147 -0.364,-3.291 3.141,-3.291 29.583,-3.291 31.254,-3.291 32.204,-4.241 34.493,-4.241 36.831,-1.902 36.831,-1.346 36.81,-1.325 pad.34@36.791,-1.325
el381: E1.292 pad.34@36.641,-0.125 U1.AE23 | length 42.8
  metal 2 w0.012: pad.34@36.641,-0.125 E1.292@36.641,-0.106
  metal1 w0.005: U1.AE23@-1.47,-1.329 -1.498,-1.356 -1.498,-2.143 -0.36,-3.281 31.259,-3.281 32.208,-4.231 34.488,-4.231 36.761,-1.958 36.761,-0.226 36.66,-0.125 pad.34@36.641,-0.125
el382: E1.315 pad.34@36.641,-0.275 U1.AE24 | length 42.5
  metal 2 w0.012: pad.34@36.641,-0.275 E1.315@36.641,-0.256
  metal1 w0.005: U1.AE24@-1.47,-1.469 -1.488,-1.486 -1.488,-2.139 -0.355,-3.271 31.263,-3.271 32.212,-4.221 34.484,-4.221 36.751,-1.954 36.751,-0.366 36.66,-0.275 pad.34@36.641,-0.275
el383: E1.338 pad.34@36.641,-0.425 U1.AE25 | length 42.1
  metal 2 w0.012: pad.34@36.641,-0.425 E1.338@36.641,-0.406
  metal1 w0.005: U1.AE25@-1.47,-1.609 -1.47,-2.142 -0.359,-3.254 31.259,-3.254 32.216,-4.211 34.48,-4.211 36.741,-1.95 36.741,-0.506 36.66,-0.425 pad.34@36.641,-0.425
el384: E1.88 pad.34@33.641,1.114 U1.D14 | length 34.1
  metal 2 w0.012: E1.88@33.641,1.094 pad.34@33.641,1.114
  metal1 w0.005: U1.D14@1.47,-0.069 1.487,-0.086 4.995,-0.086 5.704,0.622 30.141,0.622 31.7,0.622 33.2,2.122 33.425,2.122 33.701,1.846 33.701,1.154 33.66,1.114 pad.34@33.641,1.114
el385: E1.87 pad.34@33.491,1.114 U1.D15 | length 33.9
  metal 2 w0.012: E1.87@33.491,1.094 pad.34@33.491,1.114
  metal1 w0.005: U1.D15@1.47,-0.209 1.487,-0.226 5.012,-0.226 5.751,0.512 30.141,0.512 31.746,0.512 33.246,2.012 33.379,2.012 33.551,1.841 33.551,1.154 33.51,1.114 pad.34@33.491,1.114
el386: E1.342 pad.34@33.791,-0.575 U1.D18 | length 34.6
  metal 2 w0.012: pad.34@33.791,-0.575 E1.342@33.791,-0.556
  metal1 w0.005: U1.D18@1.47,-0.629 1.487,-0.646 3.141,-0.646 30.141,-0.646 31.546,-0.646 33.063,-2.164 33.641,-2.164 33.881,-1.924 33.881,-0.646 33.81,-0.575 pad.34@33.791,-0.575
el387: E1.343 pad.34@33.941,-0.575 U1.D19 | length 34.8
  metal 2 w0.012: pad.34@33.941,-0.575 E1.343@33.941,-0.556
  metal1 w0.005: U1.D19@1.47,-0.769 1.487,-0.786 30.141,-0.786 31.53,-0.786 33.019,-2.275 33.686,-2.275 34.031,-1.93 34.031,-0.646 33.96,-0.575 pad.34@33.941,-0.575
el388: E1.65 pad.34@33.641,1.264 U1.E14 | length 34
  metal 2 w0.012: E1.65@33.641,1.244 pad.34@33.641,1.264
  metal1 w0.005: U1.E14@1.33,-0.069 1.357,-0.096 5,-0.096 5.708,0.612 30.141,0.612 31.704,0.612 33.204,2.112 33.42,2.112 33.691,1.842 33.691,1.294 33.66,1.264 pad.34@33.641,1.264
el389: E1.64 pad.34@33.491,1.264 U1.E15 | length 33.8
  metal 2 w0.012: E1.64@33.491,1.244 pad.34@33.491,1.264
  metal1 w0.005: U1.E15@1.33,-0.209 1.357,-0.236 5.017,-0.236 5.755,0.502 30.141,0.502 31.75,0.502 33.25,2.002 33.375,2.002 33.541,1.837 33.541,1.294 33.51,1.264 pad.34@33.491,1.264
el390: E1.319 pad.34@33.791,-0.425 U1.E18 | length 34.9
  metal 2 w0.012: pad.34@33.791,-0.425 E1.319@33.791,-0.406
  metal1 w0.005: U1.E18@1.33,-0.629 1.357,-0.656 3.141,-0.656 30.141,-0.656 31.542,-0.656 33.059,-2.174 33.646,-2.174 33.891,-1.928 33.891,-0.506 33.81,-0.425 pad.34@33.791,-0.425
el391: E1.320 pad.34@33.941,-0.425 U1.E19 | length 35.1
  metal 2 w0.012: pad.34@33.941,-0.425 E1.320@33.941,-0.406
  metal1 w0.005: U1.E19@1.33,-0.769 1.357,-0.796 30.141,-0.796 31.526,-0.796 33.014,-2.285 33.69,-2.285 34.041,-1.934 34.041,-0.506 33.96,-0.425 pad.34@33.941,-0.425
el392: E1.42 pad.34@33.641,1.414 U1.F14 | length 34
  metal 2 w0.012: E1.42@33.641,1.394 pad.34@33.641,1.414
  metal1 w0.005: U1.F14@1.19,-0.069 1.227,-0.106 5.004,-0.106 5.712,0.602 30.141,0.602 31.708,0.602 33.208,2.102 33.416,2.102 33.681,1.838 33.681,1.434 33.66,1.414 pad.34@33.641,1.414
el393: E1.41 pad.34@33.491,1.414 U1.F15 | length 33.8
  metal 2 w0.012: E1.41@33.491,1.394 pad.34@33.491,1.414
  metal1 w0.005: U1.F15@1.19,-0.209 1.227,-0.246 5.021,-0.246 ; 5.022,-0.246 5.76,0.492 30.141,0.492 31.754,0.492 33.254,1.992 33.371,1.992 33.531,1.832 33.531,1.434 33.51,1.414 pad.34@33.491,1.414
el394: E1.271 pad.34@33.491,-0.125 U1.F16 | length 35
  metal 2 w0.012: pad.34@33.491,-0.125 E1.271@33.491,-0.106
  metal1 w0.005: U1.F16@1.19,-0.349 1.227,-0.386 3.141,-0.386 30.141,-0.386 31.54,-0.386 33.137,-1.983 33.555,-1.983 33.611,-1.927 33.611,-0.226 33.51,-0.125 pad.34@33.491,-0.125
el395: E1.295 pad.34@33.641,-0.275 U1.F17 | length 35
  metal 2 w0.012: pad.34@33.641,-0.275 E1.295@33.641,-0.256
  metal1 w0.005: U1.F17@1.19,-0.489 1.227,-0.526 31.553,-0.526 33.1,-2.074 33.604,-2.074 33.751,-1.927 33.751,-0.366 33.66,-0.275 pad.34@33.641,-0.275
el396: E1.296 pad.34@33.791,-0.275 U1.F18 | length 35.2
  metal 2 w0.012: pad.34@33.791,-0.275 E1.296@33.791,-0.256
  metal1 w0.005: U1.F18@1.19,-0.629 1.227,-0.666 3.141,-0.666 30.141,-0.666 31.537,-0.666 33.055,-2.184 33.65,-2.184 33.901,-1.932 33.901,-0.366 33.81,-0.275 pad.34@33.791,-0.275
el397: E1.297 pad.34@33.941,-0.275 U1.F19 | length 35.4
  metal 2 w0.012: pad.34@33.941,-0.275 E1.297@33.941,-0.256
  metal1 w0.005: U1.F19@1.19,-0.769 1.227,-0.806 30.141,-0.806 31.522,-0.806 33.01,-2.295 33.694,-2.295 34.051,-1.938 34.051,-0.366 33.96,-0.275 pad.34@33.941,-0.275
el398: E1.20 pad.34@33.641,1.564 U1.G14 | length 34
  metal 2 w0.012: E1.20@33.641,1.544 pad.34@33.641,1.564
  metal1 w0.005: U1.G14@1.05,-0.069 1.097,-0.116 5.008,-0.116 5.716,0.592 30.141,0.592 31.713,0.592 33.213,2.092 33.412,2.092 33.671,1.834 33.671,1.594 pad.34@33.641,1.564
el399: E1.455 pad.34@33.491,-1.325 U1.G15 | length 33.8
  metal 2 w0.012: pad.34@33.491,-1.325 E1.455@33.491,-1.306
  metal1 w0.005: U1.G15@1.05,-0.209 1.097,-0.256 5.025,-0.256 31.523,-0.256 33.17,-1.903 33.522,-1.903 33.531,-1.894 33.531,-1.346 ; pad.34@33.491,-1.325 33.51,-1.325 33.531,-1.345
el400: E1.478 pad.34@33.641,-1.475 U1.G16 | length 33.8
  metal 2 w0.012: pad.34@33.641,-1.475 E1.478@33.641,-1.456
  metal1 w0.005: U1.G16@1.05,-0.349 1.097,-0.396 3.141,-0.396 30.141,-0.396 31.536,-0.396 33.134,-1.994 33.571,-1.994 33.671,-1.894 33.671,-1.505 pad.34@33.641,-1.475
el401: E1.272 pad.34@33.641,-0.125 U1.G17 | length 35.3
  metal 2 w0.012: pad.34@33.641,-0.125 E1.272@33.641,-0.106
  metal1 w0.005: U1.G17@1.05,-0.489 1.097,-0.536 31.549,-0.536 33.096,-2.084 33.608,-2.084 33.761,-1.931 33.761,-0.226 33.66,-0.125 pad.34@33.641,-0.125
el402: E1.273 pad.34@33.791,-0.125 U1.G18 | length 35.5
  metal 2 w0.012: pad.34@33.791,-0.125 E1.273@33.791,-0.106
  metal1 w0.005: U1.G18@1.05,-0.629 1.097,-0.676 3.141,-0.676 31.533,-0.676 33.051,-2.194 33.654,-2.194 33.911,-1.936 33.911,-0.226 33.81,-0.125 pad.34@33.791,-0.125
el403: E1.274 pad.34@33.941,-0.125 U1.G19 | length 35.7
  metal 2 w0.012: pad.34@33.941,-0.125 E1.274@33.941,-0.106
  metal1 w0.005: U1.G19@1.05,-0.769 1.097,-0.816 31.518,-0.816 33.006,-2.305 33.698,-2.305 34.061,-1.942 34.061,-0.226 33.96,-0.125 pad.34@33.941,-0.125
el404: E1.248 pad.34@33.491,0.064 U1.H14 | length 35.6
  metal 2 w0.012: E1.248@33.491,0.044 pad.34@33.491,0.064
  metal1 w0.005: U1.H14@0.91,-0.069 0.967,-0.126 5.012,-0.126 5.721,0.582 30.141,0.582 31.717,0.582 33.217,2.082 33.408,2.082 33.621,1.87 33.621,0.174 33.51,0.064 pad.34@33.491,0.064
el405: E1.432 pad.34@33.491,-1.175 U1.H15 | length 34.1
  metal 2 w0.012: pad.34@33.491,-1.175 E1.432@33.491,-1.156
  metal1 w0.005: U1.H15@0.91,-0.209 0.967,-0.266 5.029,-0.266 31.519,-0.266 33.166,-1.913 33.526,-1.913 33.541,-1.898 33.541,-1.206 33.51,-1.175 pad.34@33.491,-1.175
el406: E1.456 pad.34@33.641,-1.325 U1.H16 | length 34.1
  metal 2 w0.012: pad.34@33.641,-1.325 E1.456@33.641,-1.306
  metal1 w0.005: U1.H16@0.91,-0.349 0.967,-0.406 3.141,-0.406 30.141,-0.406 31.532,-0.406 33.129,-2.004 33.575,-2.004 33.681,-1.898 33.681,-1.346 ; pad.34@33.641,-1.325 33.66,-1.325 33.681,-1.345
el407: E1.499 pad.34@33.791,-1.625 U1.H17 | length 33.9
  metal 2 w0.012: pad.34@33.791,-1.625 E1.499@33.791,-1.606
  metal1 w0.005: U1.H17@0.91,-0.489 0.967,-0.546 3.141,-0.546 30.141,-0.546 31.545,-0.546 33.092,-2.094 33.612,-2.094 33.811,-1.895 33.811,-1.645 pad.34@33.791,-1.625
el408: E1.500 pad.34@33.941,-1.625 U1.H18 | length 34.1
  metal 2 w0.012: pad.34@33.941,-1.625 E1.500@33.941,-1.606
  metal1 w0.005: U1.H18@0.91,-0.629 0.967,-0.686 3.141,-0.686 31.529,-0.686 33.048,-2.205 33.657,-2.205 33.961,-1.901 33.961,-1.645 pad.34@33.941,-1.625
el409: E1.501 pad.34@34.091,-1.625 U1.H19 | length 34.3
  metal 2 w0.012: pad.34@34.091,-1.625 E1.501@34.091,-1.606
  metal1 w0.005: U1.H19@0.91,-0.769 0.967,-0.826 3.141,-0.826 31.514,-0.826 33.004,-2.316 33.701,-2.316 34.111,-1.906 34.111,-1.645 pad.34@34.091,-1.625
el410: E1.225 pad.34@33.491,0.214 U1.J14 | length 35.6
  metal 2 w0.012: E1.225@33.491,0.194 pad.34@33.491,0.214
  metal1 w0.005: U1.J14@0.77,-0.069 0.837,-0.136 5.016,-0.136 5.725,0.572 31.721,0.572 33.221,2.072 33.404,2.072 33.611,1.866 33.611,0.314 33.51,0.214 pad.34@33.491,0.214
el411: E1.409 pad.34@33.491,-1.025 U1.J15 | length 34.4
  metal 2 w0.012: pad.34@33.491,-1.025 E1.409@33.491,-1.006
  metal1 w0.005: U1.J15@0.77,-0.209 0.837,-0.276 5.033,-0.276 31.515,-0.276 33.162,-1.923 33.53,-1.923 33.551,-1.902 33.551,-1.066 33.51,-1.025 pad.34@33.491,-1.025
el412: E1.433 pad.34@33.641,-1.175 U1.J16 | length 34.4
  metal 2 w0.012: pad.34@33.641,-1.175 E1.433@33.641,-1.156
  metal1 w0.005: U1.J16@0.77,-0.349 0.837,-0.416 3.141,-0.416 30.141,-0.416 31.528,-0.416 33.125,-2.014 33.579,-2.014 33.691,-1.902 33.691,-1.206 33.66,-1.175 pad.34@33.641,-1.175
el413: E1.479 pad.34@33.791,-1.475 U1.J17 | length 34.3
  metal 2 w0.012: pad.34@33.791,-1.475 E1.479@33.791,-1.456
  metal1 w0.005: U1.J17@0.77,-0.489 0.837,-0.556 3.141,-0.556 31.541,-0.556 33.088,-2.104 33.617,-2.104 33.821,-1.899 33.821,-1.505 pad.34@33.791,-1.475
el414: E1.480 pad.34@33.941,-1.475 U1.J18 | length 34.4
  metal 2 w0.012: pad.34@33.941,-1.475 E1.480@33.941,-1.456
  metal1 w0.005: U1.J18@0.77,-0.629 0.837,-0.696 3.141,-0.696 31.525,-0.696 33.043,-2.215 33.661,-2.215 33.971,-1.905 33.971,-1.505 pad.34@33.941,-1.475
el415: E1.481 pad.34@34.091,-1.475 U1.J19 | length 34.6
  metal 2 w0.012: pad.34@34.091,-1.475 E1.481@34.091,-1.456
  metal1 w0.005: U1.J19@0.77,-0.769 0.837,-0.836 3.141,-0.836 30.141,-0.836 31.509,-0.836 33,-2.326 33.705,-2.326 34.121,-1.91 34.121,-1.505 pad.34@34.091,-1.475
el416: E1.202 pad.34@33.491,0.364 U1.K14 | length 35.6
  metal 2 w0.012: E1.202@33.491,0.344 pad.34@33.491,0.364
  metal1 w0.005: U1.K14@0.63,-0.069 0.707,-0.146 5.02,-0.146 5.729,0.562 30.141,0.562 31.725,0.562 33.225,2.062 33.4,2.062 33.601,1.861 33.601,0.454 33.51,0.364 pad.34@33.491,0.364
el417: E1.386 pad.34@33.491,-0.875 U1.K15 | length 34.7
  metal 2 w0.012: pad.34@33.491,-0.875 E1.386@33.491,-0.856
  metal1 w0.005: U1.K15@0.63,-0.209 0.707,-0.286 5.037,-0.286 31.511,-0.286 33.158,-1.933 33.534,-1.933 33.561,-1.906 33.561,-0.926 33.51,-0.875 pad.34@33.491,-0.875
el418: E1.410 pad.34@33.641,-1.025 U1.K16 | length 34.8
  metal 2 w0.012: pad.34@33.641,-1.025 E1.410@33.641,-1.006
  metal1 w0.005: U1.K16@0.63,-0.349 0.707,-0.426 30.141,-0.426 31.524,-0.426 33.121,-2.024 33.583,-2.024 33.701,-1.906 33.701,-1.066 33.66,-1.025 pad.34@33.641,-1.025
el419: E1.457 pad.34@33.791,-1.325 U1.K17 | length 34.6
  metal 2 w0.012: pad.34@33.791,-1.325 E1.457@33.791,-1.306
  metal1 w0.005: U1.K17@0.63,-0.489 0.707,-0.566 3.141,-0.566 31.536,-0.566 33.084,-2.114 33.621,-2.114 33.831,-1.903 33.831,-1.346 33.81,-1.325 pad.34@33.791,-1.325
el420: E1.458 pad.34@33.941,-1.325 U1.K18 | length 34.8
  metal 2 w0.012: pad.34@33.941,-1.325 E1.458@33.941,-1.306
  metal1 w0.005: U1.K18@0.63,-0.629 0.707,-0.706 3.141,-0.706 31.521,-0.706 33.039,-2.225 33.665,-2.225 33.981,-1.909 33.981,-1.346 33.96,-1.325 pad.34@33.941,-1.325
el421: E1.459 pad.34@34.091,-1.325 U1.K19 | length 35
  metal 2 w0.012: pad.34@34.091,-1.325 E1.459@34.091,-1.306
  metal1 w0.005: U1.K19@0.63,-0.769 0.707,-0.846 3.141,-0.846 30.141,-0.846 31.505,-0.846 32.995,-2.336 33.709,-2.336 34.131,-1.914 34.131,-1.346 34.11,-1.325 pad.34@34.091,-1.325
el422: E1.179 pad.34@33.491,0.514 U1.L14 | length 35.5
  metal 2 w0.012: E1.179@33.491,0.494 pad.34@33.491,0.514
  metal1 w0.005: U1.L14@0.49,-0.069 0.577,-0.156 5.024,-0.156 5.733,0.552 30.141,0.552 31.729,0.552 33.229,2.052 33.396,2.052 33.591,1.857 33.591,0.594 33.51,0.514 pad.34@33.491,0.514
el423: E1.363 pad.34@33.491,-0.725 U1.L15 | length 35.1
  metal 2 w0.012: pad.34@33.491,-0.725 E1.363@33.491,-0.706
  metal1 w0.005: U1.L15@0.49,-0.209 0.577,-0.296 5.041,-0.296 31.507,-0.296 33.153,-1.943 33.539,-1.943 33.571,-1.91 33.571,-0.786 33.51,-0.725 pad.34@33.491,-0.725
el424: E1.387 pad.34@33.641,-0.875 U1.L16 | length 35.1
  metal 2 w0.012: pad.34@33.641,-0.875 E1.387@33.641,-0.856
  metal1 w0.005: U1.L16@0.49,-0.349 0.577,-0.436 30.141,-0.436 31.52,-0.436 33.117,-2.034 33.588,-2.034 33.711,-1.91 33.711,-0.926 33.66,-0.875 pad.34@33.641,-0.875
el425: E1.434 pad.34@33.791,-1.175 U1.L17 | length 34.9
  metal 2 w0.012: pad.34@33.791,-1.175 E1.434@33.791,-1.156
  metal1 w0.005: U1.L17@0.49,-0.489 0.577,-0.576 3.141,-0.576 31.532,-0.576 33.08,-2.124 33.625,-2.124 33.841,-1.907 33.841,-1.206 33.81,-1.175 pad.34@33.791,-1.175
el426: E1.435 pad.34@33.941,-1.175 U1.L18 | length 35.1
  metal 2 w0.012: pad.34@33.941,-1.175 E1.435@33.941,-1.156
  metal1 w0.005: U1.L18@0.49,-0.629 0.577,-0.716 3.141,-0.716 31.517,-0.716 33.035,-2.235 33.669,-2.235 33.991,-1.913 33.991,-1.206 33.96,-1.175 pad.34@33.941,-1.175
el427: E1.436 pad.34@34.091,-1.175 U1.L19 | length 35.3
  metal 2 w0.012: pad.34@34.091,-1.175 E1.436@34.091,-1.156
  metal1 w0.005: U1.L19@0.49,-0.769 0.577,-0.856 3.141,-0.856 30.141,-0.856 31.501,-0.856 32.991,-2.346 33.713,-2.346 34.141,-1.919 34.141,-1.206 34.11,-1.175 pad.34@34.091,-1.175
el428: E1.156 pad.34@33.491,0.664 U1.M14 | length 35.5
  metal 2 w0.012: E1.156@33.491,0.644 pad.34@33.491,0.664
  metal1 w0.005: U1.M14@0.35,-0.069 0.447,-0.166 5.029,-0.166 5.737,0.542 30.141,0.542 31.733,0.542 33.233,2.042 33.391,2.042 33.581,1.853 33.581,0.734 33.51,0.664 pad.34@33.491,0.664
el429: E1.340 pad.34@33.491,-0.575 U1.M15 | length 35.4
  metal 2 w0.012: pad.34@33.491,-0.575 E1.340@33.491,-0.556
  metal1 w0.005: U1.M15@0.35,-0.209 0.447,-0.306 5.046,-0.306 31.503,-0.306 33.149,-1.953 33.543,-1.953 33.581,-1.914 33.581,-0.646 33.51,-0.575 pad.34@33.491,-0.575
